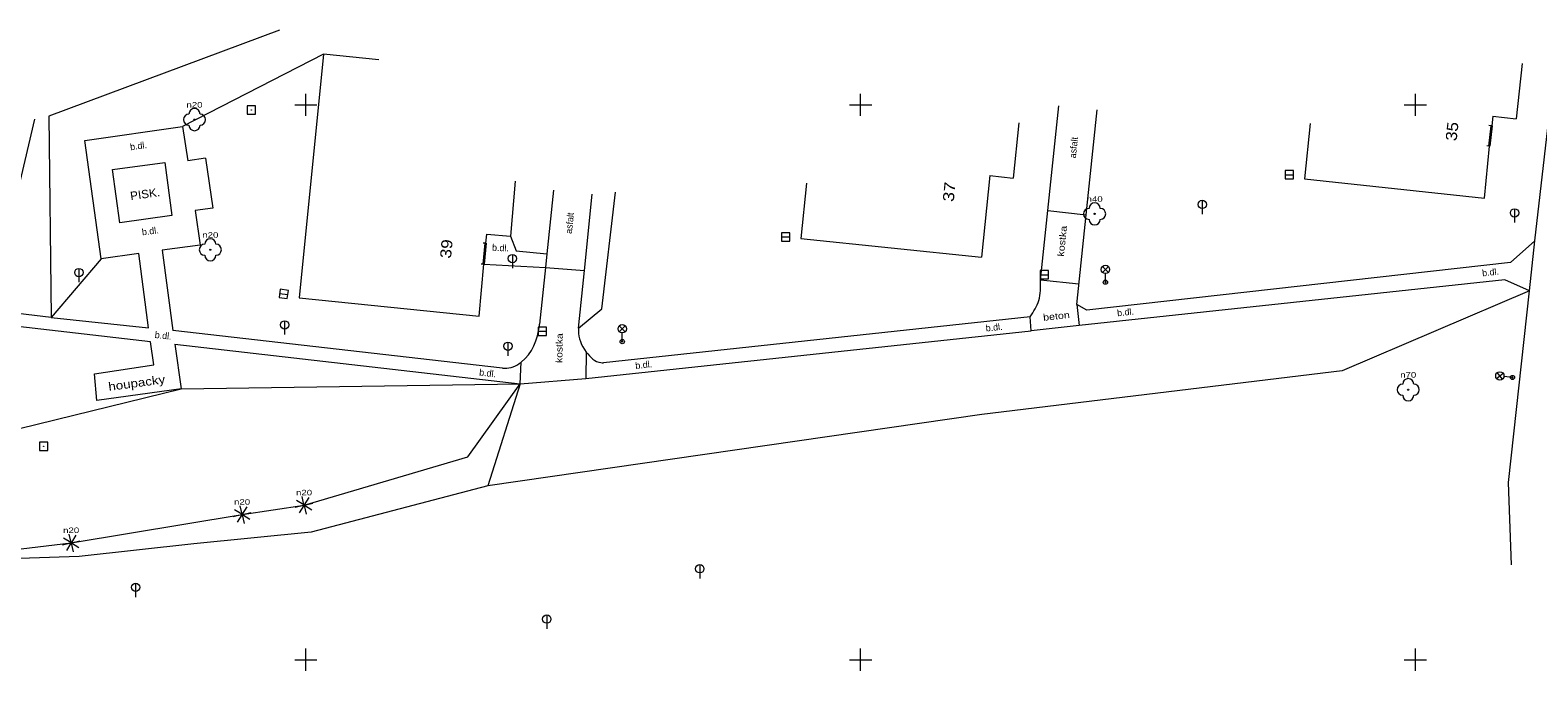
# Model space of a CAD drawing. Extents: x -670514 to -669423, y -1130798 to -1130123.
# Drawn here: x -670074.8 to -669939, y -1130651 to -1130593.3 of the extents above; entities that cross this region are included whole.
import ezdxf
from ezdxf.enums import TextEntityAlignment as Align

# ---------------------------------------------------------------- set-up
doc = ezdxf.new("R2010")
doc.units = 0
doc.header["$LTSCALE"] = 0.24
for name, color, linetype, lineweight in [('10', 7, 'Continuous', 13), ('11', 7, 'Continuous', 13), ('14', 7, 'Continuous', 13), ('22', 7, 'Continuous', 13), ('26', 7, 'Continuous', 13), ('27', 7, 'Continuous', 13), ('33', 7, 'Continuous', 13), ('5', 7, 'Continuous', 13), ('6', 7, 'Continuous', 13), ('61', 7, 'Continuous', 13)]:
    doc.layers.add(name, color=color, linetype=linetype, lineweight=lineweight)
for name, color, linetype in [('40', 7, 'Continuous'), ('42', 7, 'Continuous'), ('44', 7, 'Continuous')]:
    doc.layers.add(name, color=color, linetype=linetype)

msp = doc.modelspace()

# ---------------------------------------------------------------- linework, layer by layer
at = {"layer": '10'}
for p, q in [((-669983.791, -1130615.788), (-669982.14, -1130600.082)), ((-670059.058, -1130604.817), (-670060.64, -1130605.055)), ((-670059.058, -1130604.817), (-670058.398, -1130609.298)), ((-670058.398, -1130609.298), (-670059.981, -1130609.533)), ((-669941.429, -1130614.191), (-669939.235, -1130612.262)), ((-670033.959, -1130614.367), (-670028.396, -1130614.648)), ((-670072.966, -1130619.156), (-670064.174, -1130620.085)), ((-669984.718, -1130619.095), (-670023.174, -1130623.232)), ((-670032.262, -1130623.724), (-670061.993, -1130620.33)), ((-670024.765, -1130624.654), (-669984.614, -1130620.361))]:
    msp.add_line(p, q, dxfattribs=at)
for points in [[(-669941.429, -1130614.191), (-669979.6, -1130618.509), (-669980.513, -1130617.991), (-669979.661, -1130609.898), (-669978.666, -1130600.448)], [(-669941.351, -1130641.441), (-669941.595, -1130634.042), (-669939.703, -1130616.745), (-669939.235, -1130612.262), (-669937.892, -1130600.497)], [(-670072.966, -1130619.156), (-670078.479, -1130618.498), (-670074.424, -1130601.288)], [(-670068.438, -1130613.875), (-670069.925, -1130603.202), (-670061.107, -1130601.956), (-670060.64, -1130605.055)], [(-670027.666, -1130607.697), (-670028.279, -1130613.41), (-670028.396, -1130614.648), (-670028.929, -1130619.763)], [(-670025.417, -1130620.108), (-670024.894, -1130614.94), (-670024.205, -1130608.045)], [(-670059.981, -1130609.533), (-670059.52, -1130612.644), (-670062.963, -1130613.104), (-670061.993, -1130620.33)], [(-670031.559, -1130611.844), (-670031.044, -1130613.149), (-670028.279, -1130613.41)], [(-670064.174, -1130620.085), (-670065.054, -1130613.405), (-670068.438, -1130613.875)], [(-669939.703, -1130616.745), (-669941.94, -1130615.769), (-669980.289, -1130619.896), (-669984.614, -1130620.361)], [(-670061.814, -1130621.579), (-670061.252, -1130625.602), (-670068.842, -1130626.633), (-670069.057, -1130624.227), (-670063.713, -1130623.417), (-670063.988, -1130621.346), (-670078.329, -1130619.694)], [(-670061.814, -1130621.579), (-670030.686, -1130625.152), (-670024.765, -1130624.654)]]:
    msp.add_lwpolyline(points, dxfattribs=at)
msp.add_lwpolyline([(-670067.417, -1130605.832), (-670062.709, -1130605.194), (-670062.068, -1130609.981), (-670066.75, -1130610.64)], close=True, dxfattribs=at)
for points in [[(-669984.718, -1130619.095), (-669983.936, -1130617.623), (-669983.791, -1130615.788)], [(-670032.262, -1130623.724), (-670032.089, -1130623.739), (-670030.594, -1130623.182), (-670028.946, -1130619.909), (-670028.929, -1130619.763)], [(-670025.417, -1130620.108), (-670025.432, -1130620.336), (-670024.724, -1130622.275), (-670023.408, -1130623.227), (-670023.174, -1130623.232)]]:
    msp.add_spline(points, degree=3, dxfattribs=at)
at = {"layer": '11'}
for p, q in [((-669983.133, -1130609.533), (-669979.661, -1130609.898)), ((-670028.396, -1130614.648), (-670024.894, -1130614.94)), ((-669980.32, -1130616.153), (-669983.791, -1130615.788)), ((-669980.513, -1130617.991), (-669980.289, -1130619.896)), ((-669984.614, -1130620.361), (-669984.718, -1130619.095)), ((-670024.724, -1130622.275), (-670024.765, -1130624.654)), ((-670030.686, -1130625.152), (-670030.594, -1130623.182))]:
    msp.add_line(p, q, dxfattribs=at)
at = {"layer": '14'}
for p, q in [((-670048.405, -1130595.448), (-670061.107, -1130601.956)), ((-670068.438, -1130613.875), (-670072.966, -1130619.156)), ((-669989.062, -1130627.892), (-670033.584, -1130634.335))]:
    msp.add_line(p, q, dxfattribs=at)
for points in [[(-670052.372, -1130593.27), (-670073.159, -1130601.008), (-670072.966, -1130619.156)], [(-670025.417, -1130620.108), (-670023.312, -1130618.368), (-670022.098, -1130607.856)], [(-669939.703, -1130616.745), (-669956.609, -1130623.98), (-669989.062, -1130627.892)], [(-670114.569, -1130631.426), (-670075.797, -1130629.157), (-670061.252, -1130625.602), (-670030.686, -1130625.152)]]:
    msp.add_lwpolyline(points, dxfattribs=at)
msp.add_lwpolyline([(-670030.686, -1130625.152), (-670033.584, -1130634.335), (-670049.529, -1130638.513), (-670060.1, -1130639.57), (-670070.428, -1130640.693), (-670085.68, -1130641.204), (-670071.151, -1130639.47), (-670055.745, -1130636.915), (-670050.159, -1130636.075), (-670035.411, -1130631.719)], close=True, dxfattribs=at)
at = {"layer": '22'}
for p, q in [((-670055.753, -1130636.875), (-670055.925, -1130636.121)), ((-670055.311, -1130636.225), (-670055.725, -1130636.881)), ((-670050.953, -1130636.255), (-670050.199, -1130636.083)), ((-670050.193, -1130636.055), (-670050.849, -1130635.641)), ((-670050.179, -1130636.109), (-670050.593, -1130636.765)), ((-670050.167, -1130636.035), (-670050.339, -1130635.281)), ((-670050.151, -1130636.115), (-670049.979, -1130636.869)), ((-670049.725, -1130635.385), (-670050.139, -1130636.041)), ((-670049.469, -1130636.509), (-670050.125, -1130636.095)), ((-670050.119, -1130636.067), (-670049.365, -1130635.895)), ((-670056.539, -1130637.095), (-670055.785, -1130636.923)), ((-670055.779, -1130636.895), (-670056.435, -1130636.481)), ((-670055.765, -1130636.949), (-670056.179, -1130637.605)), ((-670055.737, -1130636.955), (-670055.565, -1130637.709)), ((-670055.055, -1130637.349), (-670055.711, -1130636.935)), ((-670055.705, -1130636.907), (-670054.951, -1130636.735)), ((-670071.159, -1130639.43), (-670071.331, -1130638.676)), ((-670070.717, -1130638.78), (-670071.131, -1130639.436)), ((-670071.945, -1130639.65), (-670071.191, -1130639.478)), ((-670071.185, -1130639.45), (-670071.841, -1130639.036)), ((-670071.171, -1130639.504), (-670071.585, -1130640.16)), ((-670071.143, -1130639.51), (-670070.971, -1130640.264)), ((-670070.461, -1130639.904), (-670071.117, -1130639.49)), ((-670071.111, -1130639.462), (-670070.357, -1130639.29))]:
    msp.add_line(p, q, dxfattribs=at)
for centre, radius in [((-670060.036, -1130601.334), 0.05), ((-669978.908, -1130609.825), 0.05), ((-670058.609, -1130613.059), 0.05), ((-669950.646, -1130625.667), 0.05), ((-670050.159, -1130636.075), 0.04), ((-670055.745, -1130636.915), 0.04), ((-670071.151, -1130639.47), 0.04)]:
    msp.add_circle(centre, radius, dxfattribs=at)
for centre, start, end in [((-670060.536, -1130601.334), 90, 270), ((-670060.036, -1130600.834), 0, 180), ((-670059.536, -1130601.334), 270, 90), ((-670060.036, -1130601.834), 180, 0), ((-669978.908, -1130609.325), 0, 180), ((-669979.408, -1130609.825), 90, 270), ((-669978.908, -1130610.325), 180, 0), ((-669978.408, -1130609.825), 270, 90), ((-670059.109, -1130613.059), 90, 270), ((-670058.609, -1130612.559), 0, 180), ((-670058.109, -1130613.059), 270, 90), ((-670058.609, -1130613.559), 180, 0), ((-669951.146, -1130625.667), 90, 270), ((-669950.646, -1130625.167), 0, 180), ((-669950.146, -1130625.667), 270, 90), ((-669950.646, -1130626.167), 180, 0)]:
    msp.add_arc(centre, 0.5, start, end, dxfattribs=at)
at = {"layer": '26'}
for points in [[(-670055.279, -1130600.847), (-670054.529, -1130600.847), (-670054.529, -1130600.097), (-670055.279, -1130600.097)], [(-670074, -1130631.148), (-670073.25, -1130631.148), (-670073.25, -1130630.398), (-670074, -1130630.398)]]:
    msp.add_lwpolyline(points, close=True, dxfattribs=at)
for centre in [(-670054.9039, -1130600.472), (-670073.6249, -1130630.773)]:
    msp.add_circle(centre, 0.02, dxfattribs=at)
at = {"layer": '27'}
for p, q in [((-669961.728, -1130606.297), (-669960.978, -1130606.297)), ((-669969.207, -1130608.6), (-669969.207, -1130609.85)), ((-669941.063, -1130609.361), (-669941.063, -1130610.611)), ((-670007.142, -1130611.906), (-670006.392, -1130611.906)), ((-670031.386, -1130613.472), (-670031.386, -1130614.722)), ((-670070.458, -1130614.74), (-670070.458, -1130615.99)), ((-669983.824, -1130615.314), (-669983.074, -1130615.314)), ((-670052.362, -1130616.986), (-670051.618, -1130617.092)), ((-670051.913, -1130619.453), (-670051.913, -1130620.703)), ((-670029.059, -1130620.406), (-670028.309, -1130620.406)), ((-670031.782, -1130621.371), (-670031.782, -1130622.621)), ((-670014.494, -1130641.428), (-670014.494, -1130642.678)), ((-670065.339, -1130643.097), (-670065.339, -1130644.347)), ((-670028.288, -1130645.968), (-670028.288, -1130647.218))]:
    msp.add_line(p, q, dxfattribs=at)
for points in [[(-669961.728, -1130606.671), (-669960.978, -1130606.671), (-669960.978, -1130605.921), (-669961.728, -1130605.921)], [(-670007.142, -1130612.28), (-670006.392, -1130612.28), (-670006.392, -1130611.53), (-670007.142, -1130611.53)], [(-669983.824, -1130615.688), (-669983.074, -1130615.688), (-669983.074, -1130614.938), (-669983.824, -1130614.938)], [(-670052.414, -1130617.356), (-670051.672, -1130617.462), (-670051.565, -1130616.72), (-670052.308, -1130616.614)], [(-670029.059, -1130620.78), (-670028.309, -1130620.78), (-670028.309, -1130620.03), (-670029.059, -1130620.03)]]:
    msp.add_lwpolyline(points, close=True, dxfattribs=at)
for centre in [(-669969.2066, -1130608.9751), (-669941.0626, -1130609.7361), (-670031.3856, -1130613.8471), (-670070.4576, -1130615.1151), (-670051.9126, -1130619.8281), (-670031.7816, -1130621.7461), (-670014.4936, -1130641.8031), (-670065.3386, -1130643.4721), (-670028.2876, -1130646.3431)]:
    msp.add_circle(centre, 0.375, dxfattribs=at)
at = {"layer": '33'}
for p, q in [((-669978.201, -1130614.567), (-669977.671, -1130615.097)), ((-669978.201, -1130615.097), (-669977.671, -1130614.567)), ((-669977.936, -1130615.982), (-669977.936, -1130615.207)), ((-670021.749, -1130619.915), (-670021.219, -1130620.445)), ((-670021.749, -1130620.445), (-670021.219, -1130619.915)), ((-670021.484, -1130621.33), (-670021.484, -1130620.555)), ((-669942.685, -1130624.652), (-669942.094, -1130624.192)), ((-669942.159, -1130624.718), (-669942.619, -1130624.126)), ((-669941.248, -1130624.564), (-669942.017, -1130624.468))]:
    msp.add_line(p, q, dxfattribs=at)
for centre, radius in [((-669977.936, -1130614.832), 0.375), ((-669977.936, -1130615.982), 0.19), ((-669977.936, -1130615.982), 0.05), ((-670021.484, -1130620.18), 0.375), ((-670021.484, -1130621.33), 0.19), ((-670021.484, -1130621.33), 0.05), ((-669942.3892, -1130624.4221), 0.375), ((-669941.248, -1130624.564), 0.19), ((-669941.248, -1130624.564), 0.05)]:
    msp.add_circle(centre, radius, dxfattribs=at)
at = {"layer": '5'}
for p, q in [((-670048.405, -1130595.448), (-670050.606, -1130617.396)), ((-670043.43, -1130595.947), (-670048.405, -1130595.448)), ((-669940.38, -1130596.286), (-669940.906, -1130601.258)), ((-669985.737, -1130601.624), (-669986.252, -1130606.597)), ((-669959.472, -1130601.691), (-669960.004, -1130606.663)), ((-669943.034, -1130601.033), (-669943.124, -1130601.888)), ((-669943.034, -1130601.033), (-669940.906, -1130601.258)), ((-669988.349, -1130606.38), (-669989.108, -1130613.725)), ((-669988.349, -1130606.38), (-669986.252, -1130606.597)), ((-670031.129, -1130606.863), (-670031.559, -1130611.844)), ((-670004.865, -1130607.07), (-670005.379, -1130612.044)), ((-670033.77, -1130612.476), (-670033.689, -1130611.66)), ((-670033.689, -1130611.66), (-670031.559, -1130611.844)), ((-670005.379, -1130612.044), (-669989.108, -1130613.725))]:
    msp.add_line(p, q, dxfattribs=at)
for points in [[(-669960.004, -1130606.663), (-669943.785, -1130608.4), (-669943.32, -1130603.734)], [(-670050.606, -1130617.396), (-670034.385, -1130619.04), (-670033.959, -1130614.367)]]:
    msp.add_lwpolyline(points, dxfattribs=at)
at = {"layer": '6'}
for p, q in [((-669943.124, -1130601.888), (-669943.373, -1130601.861)), ((-669943.32, -1130603.734), (-669943.568, -1130603.707)), ((-670033.77, -1130612.476), (-670034.019, -1130612.451)), ((-670033.959, -1130614.367), (-670034.207, -1130614.342))]:
    msp.add_line(p, q, dxfattribs=at)
at = {"layer": '6', "lineweight": 35}
for p, q in [((-669943.32, -1130603.734), (-669943.124, -1130601.888)), ((-670033.959, -1130614.367), (-670033.77, -1130612.476))]:
    msp.add_line(p, q, dxfattribs=at)
at = {"layer": '61'}
for p, q in [((-670050, -1130601), (-670050, -1130599)), ((-670000, -1130601), (-670000, -1130599)), ((-669950, -1130601), (-669950, -1130599)), ((-670051, -1130600), (-670049, -1130600)), ((-670001, -1130600), (-669999, -1130600)), ((-669951, -1130600), (-669949, -1130600)), ((-670050, -1130651), (-670050, -1130649)), ((-670000, -1130651), (-670000, -1130649)), ((-669950, -1130651), (-669950, -1130649)), ((-670051, -1130650), (-670049, -1130650)), ((-670001, -1130650), (-669999, -1130650)), ((-669951, -1130650), (-669949, -1130650))]:
    msp.add_line(p, q, dxfattribs=at)

# ---------------------------------------------------------------- texts
at = {"layer": '22', "width": 1.3}
for s, p in [('n20', (-670060.0355, -1130600.248)), ('n40', (-669978.9075, -1130608.739)), ('n20', (-670058.6085, -1130611.973)), ('n70', (-669950.6455, -1130624.581)), ('n20', (-670050.1595, -1130635.189)), ('n20', (-670055.7455, -1130636.029)), ('n20', (-670071.1515, -1130638.584))]:
    msp.add_text(s, height=0.499, dxfattribs=at).set_placement(p, align=Align.CENTER)
at = {"layer": '40'}
for s, rotation, p in [('b.dl.', 7.717, (-670065.0498, -1130603.9963)), ('asfalt', 83.989, (-669980.5076, -1130603.8809)), ('asfalt', 84.294, (-670025.9303, -1130610.6868)), ('b.dl.', 7.717, (-670063.9868, -1130611.6653)), ('b.dl.', 357.108, (-670032.4711, -1130613.1796)), ('b.dl.', 6.142, (-669943.2001, -1130615.3779)), ('b.dl.', 6.142, (-669976.0991, -1130618.9759)), ('b.dl.', 6.103, (-669987.9424, -1130620.3485)), ('b.dl.', 353.452, (-670062.8887, -1130621.0824)), ('b.dl.', 353.452, (-670033.6497, -1130624.4704)), ('b.dl.', 6.103, (-670019.5214, -1130623.7235))]:
    msp.add_text(s, height=0.6, rotation=rotation, dxfattribs=at).set_placement(p, align=Align.CENTER)
for s, rotation, width, p in [('kostka', 83.99, 1.2, (-669981.5413, -1130612.3114)), ('beton', 6.137, 1.2, (-669982.3216, -1130619.3348)), ('kostka', 89.013, 1.15, (-670026.8615, -1130621.9237))]:
    msp.add_text(s, height=0.6, rotation=rotation, dxfattribs=dict(at, width=width)).set_placement(p, align=Align.CENTER)
at = {"layer": '42'}
for s, rotation, width, p in [('PISK.', 8.012, 1.05, (-670064.4403, -1130608.4058)), ('houpacky', 7.736, 1.2, (-670065.1925, -1130625.4312))]:
    msp.add_text(s, height=0.75, rotation=rotation, dxfattribs=dict(at, width=width)).set_placement(p, align=Align.CENTER)
at = {"layer": '44'}
for s, rotation, width, p in [('35', 83.939, 1.15, (-669946.2001, -1130602.4453)), ('37', 84.1, 1.2, (-669991.5219, -1130607.8914)), ('39', 84.292, 1.15, (-670036.8402, -1130613.0252))]:
    msp.add_text(s, height=1, rotation=rotation, dxfattribs=dict(at, width=width)).set_placement(p, align=Align.CENTER)

doc.saveas('drawing.dxf')
